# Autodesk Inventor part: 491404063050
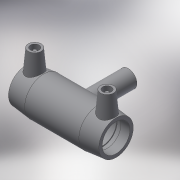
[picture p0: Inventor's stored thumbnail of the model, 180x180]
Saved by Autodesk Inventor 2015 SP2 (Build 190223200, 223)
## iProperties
Created: 2017-06
Part Number: 491404063050
Material: Generic
Description: PLASSON REDUCING TEE 63x50x63
Document SubType Name: Modeling
Designer: KIM
Mass: 57.3761 g
Surface Area: 241.06 cm^2
Volume: 57.3761 cm^3
Density: 1 g/cm^3
Appearance: Default
Author: KIM
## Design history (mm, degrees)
derived "491404.ipt"
feature "Solid1::491404.ipt"
tag "TaggingFeature1"
body "Solid1"
other parameters: "d0" = 167, "d1" = 63, "d2" = 82, "d3" = 58, "d4" = 33.4, "d5" = 73.8, "d6" = 59.85, "d7" = 63, "d8" = 168 deg, "d10" = 23.2, "d11" = 7.73333, "d13" = 167, "d14" = 17.6296, "d17" = 56.7, "d18" = 63, "d19" = 3.52592, "d20" = 168 deg, "d22" = 76.26, "d23" = 82, "d25" = 135 deg, "d26" = 116.9, "d29" = 58, "d30" = 15, "d31" = 66.8, "d34" = 5 deg, "d35" = 15, "d39" = 5 deg, "d41" = 4, "d42" = 14, "d43" = 0, "d45" = 4, "d46" = 6, "d47" = 0, "d48" = -109, "d51" = 0, "d54" = 0, "d55" = 73.8, "d56" = 82, "d57" = 58.45, "d58" = 135 deg, "d59" = 58, "d60" = 58, "d61" = 135 deg, "d62" = 109, "d72" = 75.985, "d73" = 37.9925, "d74" = -109, "d75" = 52.5, "d77" = 0, "d80" = 0, "d82" = 68, "d83" = 0, "d84" = 3, "d85" = 0, "d86" = 19.33333, "d87" = 74.7348, "d88" = 7.73333, "d89" = 3, "d90" = 0, "d_" = 63, "L_" = 167, "L_1" = 58, "D_" = 82, "A_" = 58, "d_2" = 12, "H_" = 109
